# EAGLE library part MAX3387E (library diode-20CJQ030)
Maxim's MAX3387E 3V, ±15kV ESD-Protected, AutoShutdown Plus RS-232 Transceiver for PDAs and Cell Phones General Description: The MAX3387E 3V powered EIA/TIA-232 and V.28/V.24 is a communications interface with low power requirements, high data-rate capabilities, and enhanced electrostatic discharge (ESD) protection. The MAX3387E has three receivers and three transmitters. All RS-232 inputs and outputs are protected to ±15kV using the IEC 1000-4-2 Air-Gap Discharge method, ±8kV using the IEC 1000-4-2 Contact Discharge method, and ±15kV using the Human Body Model. A proprietary low-dropout transmitter output stage enables true RS-232 performance from a +3.0V to +5.5V supply with a dual charge pump. The charge pump requires only four small 0.1µF capacitors for operation from a +3.3V supply. The MAX3387E is capable of running at data rates up to 250kbps while maintaining RS-232 compliant output levels. The MAX3387E has a unique VL pin that allows interoperation in mixed-logic voltage systems. Both input and output logic levels are pin programmable through the VL pin. The MAX3387E is available in a space-saving TSSOP package. Applications: Subnotebook/Palmtop Computers PDAs and PDA Cradles Cell Phone Data Cables Battery-Powered Equipment Hand-Held Equipment Peripherals Features: VL Pin for Compatibility with Mixed-Voltage Systems ±15kV ESD Protection on Rx Inputs and Tx Outputs Low 300µA Supply Current Guaranteed 250kbps Data Rate 1µA AutoShutdown Plus? with Receivers Active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
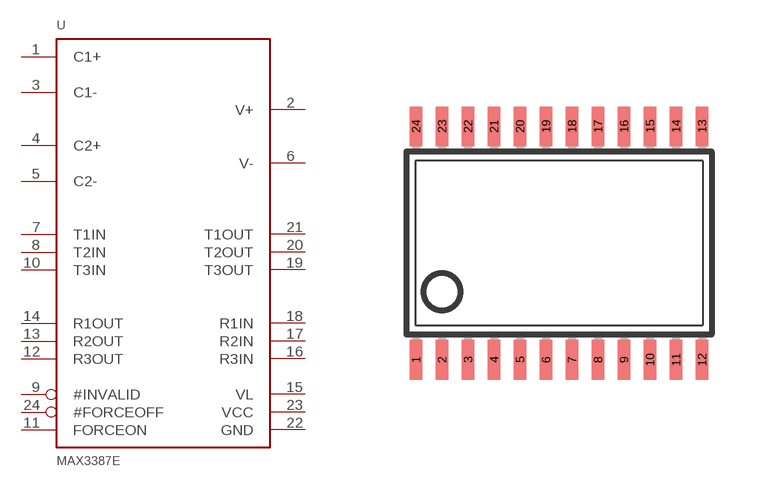
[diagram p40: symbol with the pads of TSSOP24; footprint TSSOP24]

Designator prefix U

## MAX3387E  [TSSOP24]
1  C1+  in
2  V+  in
3  C1-  in
4  C2+  in
5  C2-  in
6  V-  in
7  T1IN  in
8  T2IN  in
9  #INVALID  out
10  T3IN  in
11  FORCEON  in
12  R3OUT  out
13  R2OUT  out
14  R1OUT  out
15  VL  pwr
16  R3IN  in
17  R2IN  in
18  R1IN  in
19  T3OUT
20  T2OUT
21  T1OUT
22  GND  pwr
23  VCC  pwr
24  #FORCEOFF  in

## Footprint TSSOP24 (pad centres in mm)
Thin Shrink Small Outline Plastic 24 MAX3223-MAX3243.pdf
smd 0.305 x 0.991: 1 -3.575,-2.918; 2 -2.925,-2.918; 3 -2.275,-2.918; 4 -1.625,-2.918; 5 -0.975,-2.918; 6 -0.325,-2.918; 7 0.325,-2.918; 8 0.975,-2.918; 9 1.625,-2.918; 10 2.275,-2.918; 11 2.925,-2.918; 12 3.575,-2.918; 13 3.575,2.918; 14 2.925,2.918; 15 2.275,2.918; 16 1.625,2.918; 17 0.975,2.918; 18 0.325,2.918; 19 -0.325,2.918; 20 -0.975,2.918; 21 -1.625,2.918; 22 -2.275,2.918; 23 -2.925,2.918; 24 -3.575,2.918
